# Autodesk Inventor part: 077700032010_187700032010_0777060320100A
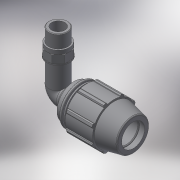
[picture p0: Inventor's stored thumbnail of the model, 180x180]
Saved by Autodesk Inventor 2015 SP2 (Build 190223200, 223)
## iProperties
Created: 2017-02
Part Number: 077700032010_187700032010_0777060320100A
Material: Generic
Description: PLASSON 90° ELBOW MALE WITH INTEGRAL BRASS THREAD 32-1"
Document SubType Name: Modeling
Designer: KIM
Mass: 174.249 g
Surface Area: 431.906 cm^2
Volume: 174.249 cm^3
Density: 1 g/cm^3
Appearance: Default
Author: KIM
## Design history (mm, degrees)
derived "07770.ipt"
feature "Solid1::07770.ipt"
tag "TaggingFeature1"
body "Solid1"
other parameters: "d2" = 32, "d4" = 8.66667, "d5" = 26, "d7" = 64, "d9" = 14.85714, "d11" = 3.46667, "d13" = 120 deg, "d14" = 44.8, "d15" = 12 deg, "d16" = 55.68, "d18" = 1.6, "d19" = 35 deg, "d20" = 17.5 deg, "d21" = 59.52, "d23" = 0, "d25" = 360 deg, "d27" = 1.28, "d33" = 0.64, "d42" = 38.48, "d43" = 1.92, "d46" = 0.96, "d51" = 104, "d68" = 6.93333, "d72" = 81, "d73" = 33.249, "d75" = 38.23635, "d76" = 23.2743, "d79" = 13.2996, "d80" = 0.99747, "d83" = 0, "d84" = 0, "d91" = 48, "d93" = 67, "d94" = 33.249, "d95" = 23.2743, "d96" = 6.93333, "d97" = 50 deg, "d98" = 1.73333, "d99" = 54.0096, "d100" = 1.73333, "d101" = 1.73333, "d105" = 2, "d106" = 39.8988, "d108" = 12, "d109" = 0, "d_" = 32, "E_" = 64, "A_" = 104, "l_" = 67, "A_1" = 81, "R_" = 33.249
